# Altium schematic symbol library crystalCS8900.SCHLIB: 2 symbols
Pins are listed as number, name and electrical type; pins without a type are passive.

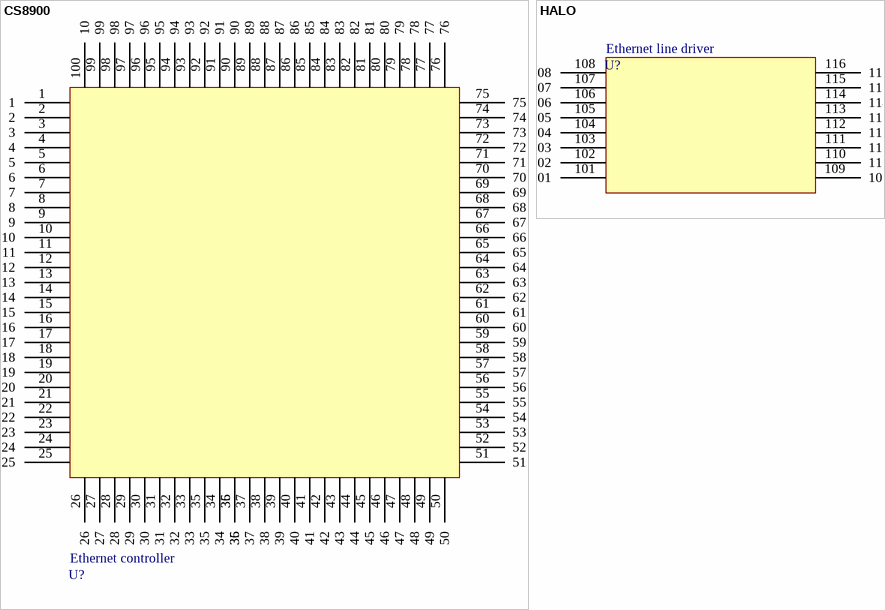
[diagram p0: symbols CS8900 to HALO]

## CS8900
designator U?, comment Ethernet controller
Chip for controlling ethernet communication
footprint Model Name (Model Description)
pins: 1, 2, 3, 4, 5, 6, 7, 8, 9, 10, 11, 12, 13, 14, 15, 16, 17, 18, 19, 20, 21, 22, 23, 24, 25, 26, 27, 28, 29, 30, 31, 32, 33, 34, 35, 35, 36, 37, 38, 39, 40, 41, 42, 43, 44, 45, 46, 47, 48, 49, 50, 51, 52, 53, 54, 55, 56, 57, 58, 59, 60, 61, 62, 63, 64, 65, 66, 67, 68, 69, 70, 71, 72, 73, 74, 75, 76, 77, 78, 79, 80, 81, 82, 83, 84, 85, 86, 87, 88, 89, 90, 91, 92, 93, 94, 95, 96, 97, 98, 99, 100

## HALO
designator U?, comment Ethernet line driver
Changes voltages
pins: 101, 102, 103, 104, 105, 106, 107, 108, 109, 110, 111, 112, 113, 114, 115, 116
